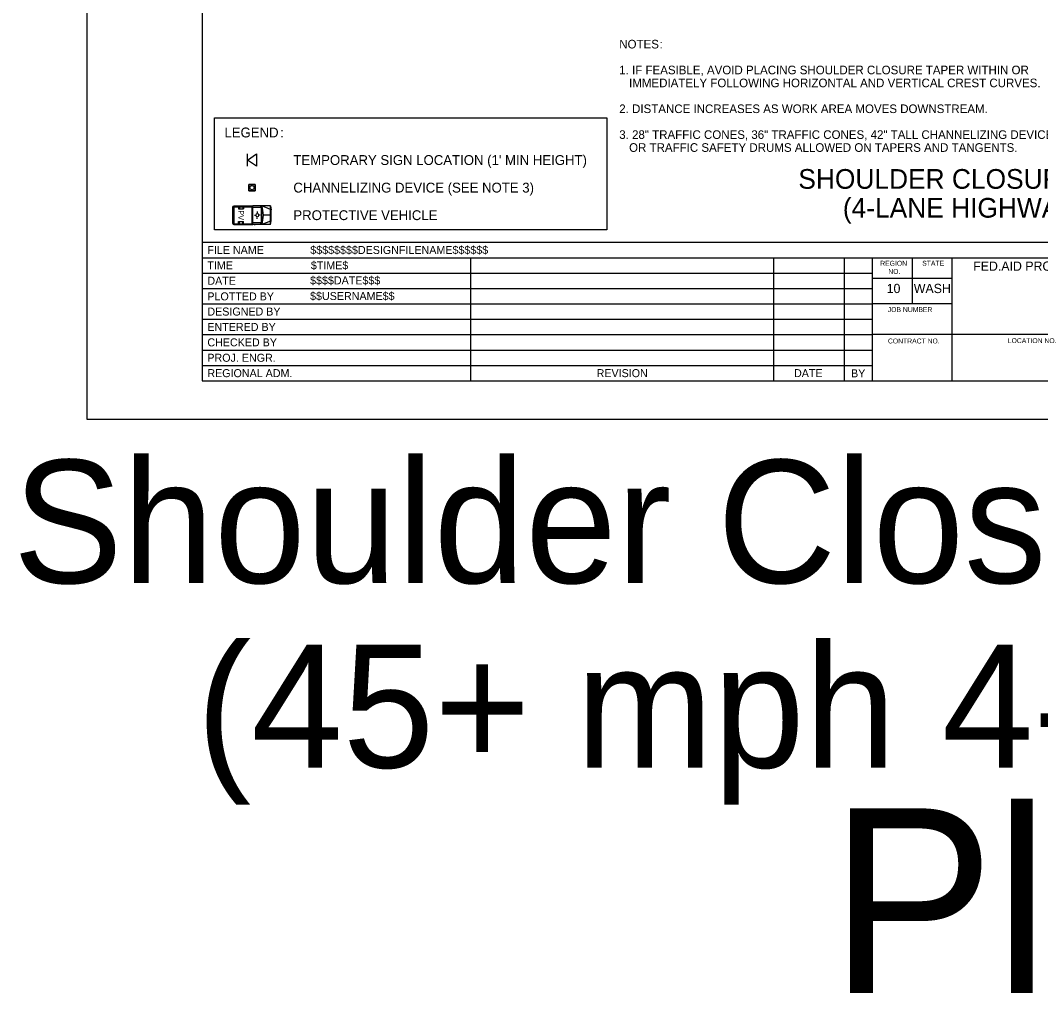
# Model space of a CAD drawing. Extents: x 99999.1 to 100096.1, y 99995 to 100010.7.
# Drawn here: x 100018.52 to 100026.81, y 99995.01 to 100002.93 of the extents above; entities that cross this region are included whole.
import ezdxf

# ---------------------------------------------------------------- set-up
doc = ezdxf.new("R2010")
doc.units = 0
for name, color, linetype in [('SH_DE_DetailHeading1Text', 7, 'Continuous'), ('SH_GI_GeneralNotesBodyText', 7, 'Continuous'), ('SH_GI_PlotLimits', 7, 'Continuous'), ('SH_GI_SheetBorder', 7, 'Continuous'), ('SH_GI_SheetLocationText', 7, 'Continuous'), ('SH_GI_SheetTextInCells', 7, 'Continuous'), ('SH_GI_TitleBlockText', 7, 'Continuous'), ('TR_WZ_PortableSignMountBlk-Wht', 7, 'Continuous'), ('TR_WZ_ProtectiveVehicle', 7, 'Continuous'), ('TR_WZ_TrafficCone', 7, 'Continuous'), ('TR_WZ_WorkZoneTextCurrent', 7, 'Continuous')]:
    doc.layers.add(name, color=color, linetype=linetype)

msp = doc.modelspace()

# ---------------------------------------------------------------- linework, layer by layer
at = {"layer": 'SH_GI_PlotLimits'}
msp.add_lwpolyline([(100019.0625, 99999.6875), (100036.0625, 99999.6875), (100036.0625, 100010.6875), (100019.0625, 100010.6875)], close=True, dxfattribs=at)
at = {"layer": 'SH_GI_SheetBorder'}
for p, q in [((100020, 100010.375), (100020, 100000)), ((100020, 100001.1259), (100035.75, 100001.1259)), ((100020, 100001.0008), (100027.4566, 100001.0008)), ((100022.179, 100001.0008), (100022.179, 100000)), ((100024.641, 100001.0008), (100024.641, 100000)), ((100025.2164, 100001.0008), (100025.2164, 100000)), ((100025.4451, 100001.0008), (100025.4451, 100000)), ((100025.7719, 100000.6255), (100025.7719, 100001.0008)), ((100026.0956, 100000), (100026.0956, 100001.0008)), ((100020, 100000.8757), (100022.1821, 100000.8757)), ((100022.1821, 100000.8757), (100025.4466, 100000.8757)), ((100026.0958, 100000.831), (100025.4466, 100000.831)), ((100020, 100000.7506), (100022.1821, 100000.7506)), ((100022.1821, 100000.7506), (100025.4466, 100000.7506)), ((100020, 100000.6255), (100025.4466, 100000.6255)), ((100026.0958, 100000.6255), (100025.4466, 100000.6255)), ((100020, 100000.5004), (100025.4466, 100000.5004)), ((100020, 100000.3753), (100025.4466, 100000.3753)), ((100027.4566, 100000.3753), (100025.4466, 100000.3753)), ((100020, 100000.2502), (100025.4466, 100000.2502)), ((100020, 100000.1251), (100025.4466, 100000.1251)), ((100020, 100000), (100035.75, 100000))]:
    msp.add_line(p, q, dxfattribs=at)
at = {"layer": 'TR_WZ_PortableSignMountBlk-Wht'}
msp.add_line((100020.3682, 100001.7439), (100020.3682, 100001.8439), dxfattribs=at)
msp.add_lwpolyline([(100020.3682, 100001.7938), (100020.44, 100001.8439), (100020.44, 100001.7439)], close=True, dxfattribs=at)
at = {"layer": 'TR_WZ_ProtectiveVehicle'}
for p, q in [((100020.248, 100001.2779), (100020.248, 100001.4138)), ((100020.2514, 100001.4184), (100020.2547, 100001.4184)), ((100020.2547, 100001.2733), (100020.2547, 100001.4184)), ((100020.2552, 100001.4208), (100020.4095, 100001.4208)), ((100020.2552, 100001.2708), (100020.2552, 100001.4208)), ((100020.2596, 100001.2768), (100020.2596, 100001.4149)), ((100020.2596, 100001.4149), (100020.4052, 100001.4149)), ((100020.2944, 100001.4149), (100020.2944, 100001.3976)), ((100020.2944, 100001.3976), (100020.3356, 100001.3976)), ((100020.3026, 100001.4149), (100020.3026, 100001.3976)), ((100020.3281, 100001.4149), (100020.3281, 100001.3976)), ((100020.3356, 100001.4149), (100020.3356, 100001.3976)), ((100020.4052, 100001.2768), (100020.4052, 100001.4149)), ((100020.4095, 100001.2708), (100020.4095, 100001.4208)), ((100020.4116, 100001.2708), (100020.4116, 100001.4208)), ((100020.5533, 100001.4208), (100020.4116, 100001.4208)), ((100020.4811, 100001.4092), (100020.4116, 100001.4092)), ((100020.4309, 100001.423), (100020.4224, 100001.423)), ((100020.4466, 100001.3747), (100020.4468, 100001.3634)), ((100020.4737, 100001.4092), (100020.4811, 100001.4208)), ((100020.4811, 100001.2708), (100020.4811, 100001.4208)), ((100020.4824, 100001.2708), (100020.4824, 100001.4208)), ((100020.5533, 100001.3934), (100020.4824, 100001.4208)), ((100020.5533, 100001.2708), (100020.5533, 100001.4208)), ((100020.5533, 100001.4208), (100020.5602, 100001.3906)), ((100020.5602, 100001.3011), (100020.5602, 100001.3906)), ((100020.248, 100001.3564), (100020.2547, 100001.3536)), ((100020.248, 100001.3353), (100020.2547, 100001.3381)), ((100020.2498, 100001.3458), (100020.2529, 100001.3458)), ((100020.2514, 100001.3437), (100020.2514, 100001.348)), ((100020.2944, 100001.2941), (100020.3356, 100001.2941)), ((100020.2944, 100001.2768), (100020.2944, 100001.2941)), ((100020.3026, 100001.2768), (100020.3026, 100001.2941)), ((100020.3281, 100001.2768), (100020.3281, 100001.2941)), ((100020.3356, 100001.2768), (100020.3356, 100001.2941)), ((100020.4811, 100001.2825), (100020.4116, 100001.2825)), ((100020.424, 100001.3464), (100020.4352, 100001.3461)), ((100020.4366, 100001.3461), (100020.4366, 100001.3461)), ((100020.4471, 100001.3161), (100020.4471, 100001.3282)), ((100020.4698, 100001.3457), (100020.4603, 100001.3458)), ((100020.4811, 100001.2708), (100020.4721, 100001.2825)), ((100020.5533, 100001.2983), (100020.4824, 100001.2708)), ((100020.5533, 100001.3458), (100020.4963, 100001.3458)), ((100020.5533, 100001.2708), (100020.5602, 100001.3011)), ((100020.2514, 100001.2733), (100020.2547, 100001.2733)), ((100020.2552, 100001.2708), (100020.4095, 100001.2708)), ((100020.2596, 100001.2768), (100020.4052, 100001.2768)), ((100020.5533, 100001.2708), (100020.4116, 100001.2708)), ((100020.4309, 100001.2687), (100020.4224, 100001.2687))]:
    msp.add_line(p, q, dxfattribs=at)
for centre, major_axis, start_param, end_param in [((100020.2514, 100001.4138), (0, 0.00458), 0, 1.570796), ((100020.3812, 100001.3459), (0, 0.1574), 4.215667, 5.208926), ((100020.2514, 100001.2779), (0, -0.00458), 4.712389, 6.283185)]:
    msp.add_ellipse(centre, major_axis=major_axis, ratio=0.73155, start_param=start_param, end_param=end_param, dxfattribs=at)
for centre, major_axis in [((100020.2514, 100001.3458), (0, -0.00211)), ((100020.4471, 100001.3458), (0, -0.0144))]:
    msp.add_ellipse(centre, major_axis=major_axis, ratio=0.73155, dxfattribs=at)
at = {"layer": 'TR_WZ_TrafficCone'}
for points in [[(100020.4308, 100001.5966), (100020.4308, 100001.5432), (100020.3775, 100001.5432), (100020.3775, 100001.5966), (100020.4308, 100001.5966)], [(100020.3775, 100001.5966), (100020.3775, 100001.5432), (100020.4308, 100001.5432), (100020.4308, 100001.5966), (100020.3775, 100001.5966)]]:
    msp.add_lwpolyline(points, dxfattribs=at)
msp.add_circle((100020.4041, 100001.5699), 0.0167, dxfattribs=at)
at = {"layer": 'TR_WZ_WorkZoneTextCurrent'}
msp.add_lwpolyline([(100020.1, 100002.1379), (100023.2886, 100002.1379), (100023.2886, 100001.2259), (100020.1, 100001.2259)], close=True, dxfattribs=at)

# ---------------------------------------------------------------- texts
at = {"layer": 'SH_DE_DetailHeading1Text'}
for s, p in [('SHOULDER CLOSURE WITH ENCROACHMENT', (100024.8442, 100001.5606)), ('(4-LANE HIGHWAYS, 40 MPH OR LESS)', (100025.2059, 100001.3259))]:
    msp.add_text(s, height=0.16, rotation=360, dxfattribs=at).set_placement(p)
at = {"layer": 'SH_GI_GeneralNotesBodyText'}
for s, p in [('NOTES', (100023.3886, 100002.7006)), (':', (100023.7161, 100002.7006)), ('1. IF FEASIBLE, AVOID PLACING SHOULDER CLOSURE TAPER WITHIN OR ', (100023.3886, 100002.4906)), ('IMMEDIATELY FOLLOWING HORIZONTAL AND VERTICAL CREST CURVES.', (100023.4686, 100002.3856)), ('2. DISTANCE INCREASES AS WORK AREA MOVES DOWNSTREAM.', (100023.3886, 100002.1756)), ('3. 28" TRAFFIC CONES, 36" TRAFFIC CONES, 42" TALL CHANNELIZING DEVICES, ', (100023.3886, 100001.9656)), ('OR TRAFFIC SAFETY DRUMS ALLOWED ON TAPERS AND TANGENTS.', (100023.4686, 100001.8606))]:
    msp.add_text(s, height=0.07, rotation=360, dxfattribs=at).set_placement(p)
at = {"layer": 'SH_GI_SheetLocationText'}
for s, height, p in [('Shoulder Closure + Encroachment', 1, (100018.4608, 99998.3571)), ('(45+ mph 4-Lane Highways)', 1, (100019.9523, 99996.8571)), ('Plot 2', 1.5, (100025.0998, 99995.0267))]:
    msp.add_text(s, height=height, dxfattribs=at).set_placement(p)
at = {"layer": 'SH_GI_SheetTextInCells'}
for s, height, p in [('FILE NAME', 0.06505, (100020.041, 100001.0308)), ('TIME', 0.06505, (100020.041, 100000.9057)), ('REGION', 0.04003, (100025.5099, 100000.9352)), ('STATE', 0.04003, (100025.8511, 100000.9357)), ('FED.AID PROJ.NO.', 0.07506, (100026.2652, 100000.8945)), ('NO.', 0.04003, (100025.5752, 100000.869)), ('DATE', 0.06505, (100020.041, 100000.7806)), ('10', 0.07506, (100025.5621, 100000.7131)), ('WASH', 0.07506, (100025.7826, 100000.7131)), ('PLOTTED BY', 0.06505, (100020.041, 100000.6538)), ('DESIGNED BY', 0.065052, (100020.041, 100000.5304)), ('JOB NUMBER', 0.04003, (100025.5712, 100000.5587)), ('ENTERED BY', 0.06505, (100020.041, 100000.4053)), ('CHECKED BY', 0.06505, (100020.041, 100000.2802)), ('CONTRACT NO.', 0.040032, (100025.5725, 100000.3037)), ('LOCATION NO.', 0.040032, (100026.5465, 100000.3067)), ('PROJ. ENGR.', 0.065052, (100020.041, 100000.1551)), ('REGIONAL ADM.', 0.065052, (100020.041, 100000.03)), ('REVISION', 0.06505, (100023.2048, 100000.03)), ('DATE', 0.06505, (100024.8091, 100000.03)), ('BY', 0.06505, (100025.2725, 100000.0285))]:
    msp.add_text(s, height=height, dxfattribs=at).set_placement(p)
at = {"layer": 'SH_GI_TitleBlockText'}
for s, height, p in [('$$$$$$$$DESIGNFILENAME$$$$$$', 0.065052, (100020.8775, 100001.0308)), ('$TIME$', 0.06505, (100020.882, 100000.9059)), ('$$$$DATE$$$', 0.065052, (100020.8759, 100000.7835)), ('$$USERNAME$$', 0.065052, (100020.8759, 100000.6567))]:
    msp.add_text(s, height=height, dxfattribs=at).set_placement(p)
at = {"layer": 'TR_WZ_ProtectiveVehicle'}
msp.add_text('PV', height=0.045, rotation=270, dxfattribs=at).set_placement((100020.2925, 100001.3862))
at = {"layer": 'TR_WZ_WorkZoneTextCurrent'}
for s, p in [('LEGEND', (100020.18, 100001.9779)), (':', (100020.6328, 100001.9779)), ("TEMPORARY SIGN LOCATION (1' MIN HEIGHT)", (100020.74, 100001.7539)), ('CHANNELIZING DEVICE (SEE NOTE 3)', (100020.74, 100001.5299)), ('PROTECTIVE VEHICLE', (100020.74, 100001.3059))]:
    msp.add_text(s, height=0.08, rotation=360, dxfattribs=at).set_placement(p)

doc.saveas('drawing.dxf')
